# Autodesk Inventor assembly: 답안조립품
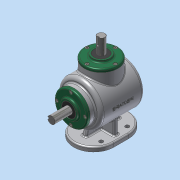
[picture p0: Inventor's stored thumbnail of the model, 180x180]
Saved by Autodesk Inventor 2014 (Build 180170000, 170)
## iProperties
Created: 2023-01
Part Number: 답안조립품
Document SubType Name: Assembly
Designer: dg
Author: dg
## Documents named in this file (14)
- C:\Users\dg\Desktop\730106V1023\답안조립품.iam
- C:\Users\dg\Desktop\730106V1023\본체.ipt
- C:\Users\dg\Desktop\730106V1023\메인 베벨기어.ipt
- C:\Users\dg\Desktop\730106V1023\메인 축.ipt
- 메인 축.ipt
- C:\Users\dg\Desktop\730106V1023\오일실 17 32 8.ipt
- C:\Users\dg\Desktop\730106V1023\커버.ipt
- C:\Users\dg\Desktop\730106V1023\키 5x5.ipt
- C:\Users\dg\Desktop\730106V1023\베어링 6203.ipt
- C:\Users\dg\Desktop\730106V1023\서브 베벨기어.ipt
- C:\Users\dg\Desktop\730106V1023\서브 축.ipt
- 서브 축.ipt
- C:\Users\dg\Desktop\730106V1023\키 4x4.ipt
- C:\Users\dg\Desktop\730106V1023\M4.ipt
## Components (8 placed, 1 different names)
1. M4:2
2. M4:3
3. M4:4
4. M4:5
5. M4:1
6. M4:6
7. M4:7
8. M4:8
